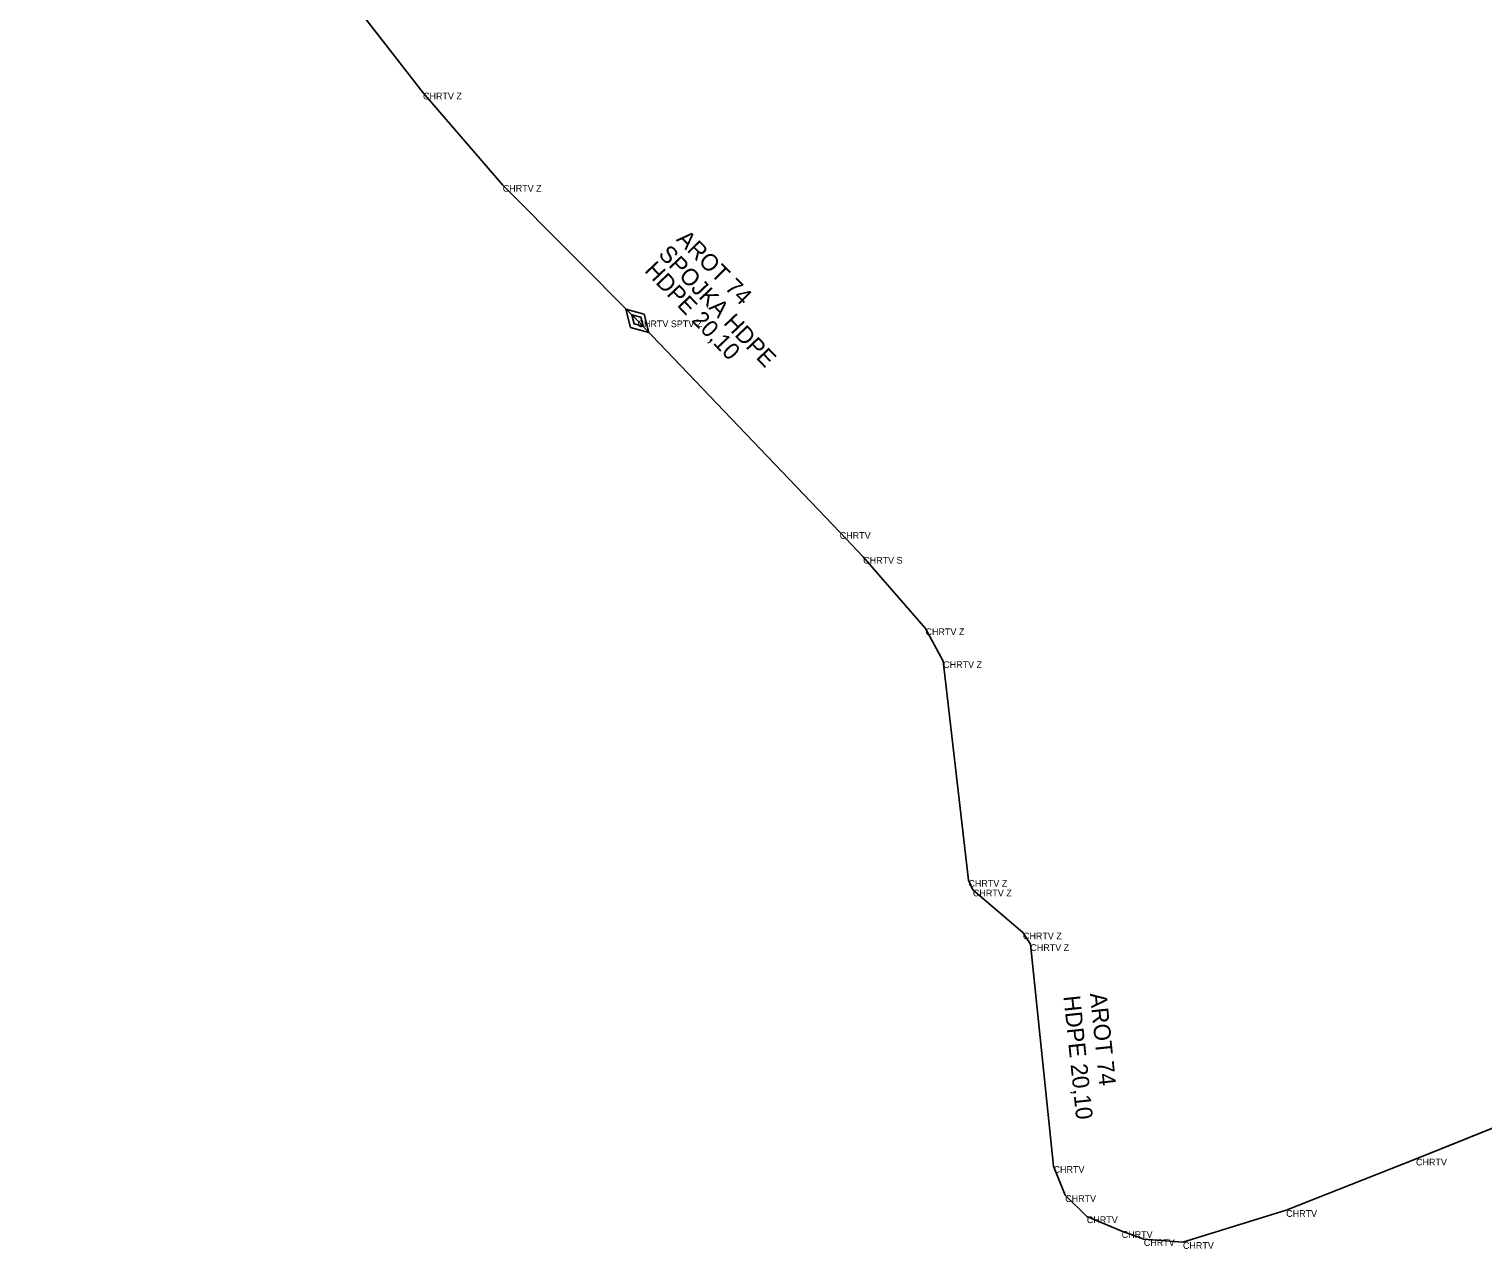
# Model space of a CAD drawing. Extents: x -651943 to -618711, y -1138561 to -1100552.
# Drawn here: x -641084.1 to -641019.1, y -1114735.4 to -1114680.8 of the extents above; entities that cross this region are included whole.
import ezdxf

# ---------------------------------------------------------------- set-up
doc = ezdxf.new("R2010")
doc.units = 0
for name, color, linetype in [('KT optika', 7, 'Continuous'), ('KT trasa', 7, 'Continuous'), ('KT zařízení', 7, 'Continuous')]:
    doc.layers.add(name, color=color, linetype=linetype)

# ---------------------------------------------------------------- blocks, each defined once
blk = doc.blocks.new('TVSPO_1')
at = {"layer": 'KT zařízení'}
for p, q in [((-0.074, 0.0016), (-0.0005, 0.0439)), ((-0.0005, -0.0409), (-0.074, 0.0016)), ((-0.0353, -0.0001), (0, 0.0203)), ((-0.0005, 0.0439), (0.0728, 0.0015)), ((0.0728, 0.0015), (-0.0005, -0.0409)), ((0, 0.0203), (0.0353, 0.0001)), ((0.0353, 0.0001), (0, -0.0204)), ((0, -0.0204), (-0.0353, -0.0001))]:
    blk.add_line(p, q, dxfattribs=at)

msp = doc.modelspace()

# ---------------------------------------------------------------- linework, layer by layer
at = {"layer": 'KT optika'}
for p, q in [((-641077, -1114670.16), (-641066.49, -1114683.68)), ((-641066.49, -1114683.68), (-641062.92, -1114687.81)), ((-641062.92, -1114687.81), (-641056.89, -1114693.87)), ((-641056.89, -1114693.87), (-641047.84, -1114703.34)), ((-641047.84, -1114703.34), (-641046.79, -1114704.45)), ((-641046.79, -1114704.45), (-641044, -1114707.65)), ((-641044, -1114707.65), (-641043.21, -1114709.12)), ((-641043.21, -1114709.12), (-641042.08, -1114718.91)), ((-641042.08, -1114718.91), (-641041.88, -1114719.34)), ((-641041.88, -1114719.34), (-641039.64, -1114721.26)), ((-641039.64, -1114721.26), (-641039.31, -1114721.78)), ((-641039.31, -1114721.78), (-641038.27, -1114731.71)), ((-641022.05, -1114731.38), (-641017.44, -1114729.53)), ((-641038.27, -1114731.71), (-641037.75, -1114733.01)), ((-641027.86, -1114733.68), (-641022.05, -1114731.38)), ((-641037.75, -1114733.01), (-641036.78, -1114733.96)), ((-641032.48, -1114735.11), (-641027.86, -1114733.68)), ((-641036.78, -1114733.96), (-641035.22, -1114734.62)), ((-641035.22, -1114734.62), (-641034.23, -1114734.98)), ((-641034.23, -1114734.98), (-641032.48, -1114735.11))]:
    msp.add_line(p, q, dxfattribs=at)
at = {"layer": 'KT trasa'}
for p, q in [((-641077, -1114670.16), (-641066.49, -1114683.68)), ((-641066.49, -1114683.68), (-641062.92, -1114687.81)), ((-641062.92, -1114687.81), (-641056.89, -1114693.87)), ((-641056.89, -1114693.87), (-641047.84, -1114703.34)), ((-641047.84, -1114703.34), (-641046.79, -1114704.45)), ((-641046.79, -1114704.45), (-641044, -1114707.65)), ((-641044, -1114707.65), (-641043.21, -1114709.12)), ((-641043.21, -1114709.12), (-641042.08, -1114718.91)), ((-641042.08, -1114718.91), (-641041.88, -1114719.34)), ((-641041.88, -1114719.34), (-641039.64, -1114721.26)), ((-641039.64, -1114721.26), (-641039.31, -1114721.78)), ((-641039.31, -1114721.78), (-641038.27, -1114731.71)), ((-641022.05, -1114731.38), (-641017.44, -1114729.53)), ((-641038.27, -1114731.71), (-641037.75, -1114733.01)), ((-641027.86, -1114733.68), (-641022.05, -1114731.38)), ((-641037.75, -1114733.01), (-641036.78, -1114733.96)), ((-641032.48, -1114735.11), (-641027.86, -1114733.68)), ((-641036.78, -1114733.96), (-641035.22, -1114734.62)), ((-641035.22, -1114734.62), (-641034.23, -1114734.98)), ((-641034.23, -1114734.98), (-641032.48, -1114735.11))]:
    msp.add_line(p, q, dxfattribs=at)
at = {"layer": 'KT zařízení'}
for points in [[(-641084.12, -1114661.06), (-641081.7, -1114663.89), (-641077, -1114670.16), (-641066.49, -1114683.68), (-641062.92, -1114687.81), (-641056.89, -1114693.87), (-641047.84, -1114703.34), (-641046.79, -1114704.45), (-641044, -1114707.65), (-641043.21, -1114709.12), (-641042.08, -1114718.91), (-641041.88, -1114719.34), (-641039.64, -1114721.26), (-641039.31, -1114721.78), (-641038.27, -1114731.71)], [(-641038.27, -1114731.71), (-641037.75, -1114733.01), (-641036.78, -1114733.96), (-641035.22, -1114734.62), (-641034.23, -1114734.98), (-641032.48, -1114735.11), (-641027.86, -1114733.68), (-641022.05, -1114731.38), (-641017.44, -1114729.53)]]:
    msp.add_lwpolyline(points, dxfattribs=at)

# ---------------------------------------------------------------- block references
at = {"layer": 'KT zařízení', "xscale": 10.000015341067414, "yscale": 10.000015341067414, "rotation": 135}
msp.add_blockref('TVSPO_1', (-641056.89, -1114693.87), dxfattribs=at)

# ---------------------------------------------------------------- texts
at = {"layer": 'KT zařízení'}
for s, p in [('CHRTV Z', (-641066.49, -1114683.98)), ('CHRTV Z', (-641062.92, -1114688.11)), ('CHRTV SPTV Z', (-641056.89, -1114694.17)), ('CHRTV', (-641047.84, -1114703.64)), ('CHRTV S', (-641046.79, -1114704.75)), ('CHRTV Z', (-641044, -1114707.95)), ('CHRTV Z', (-641043.21, -1114709.42)), ('CHRTV Z', (-641042.08, -1114719.21)), ('CHRTV Z', (-641041.88, -1114719.64)), ('CHRTV Z', (-641039.64, -1114721.56)), ('CHRTV Z', (-641039.31, -1114722.08)), ('CHRTV', (-641038.27, -1114732.01)), ('CHRTV', (-641022.05, -1114731.68)), ('CHRTV', (-641037.75, -1114733.31)), ('CHRTV', (-641027.86, -1114733.98)), ('CHRTV', (-641036.78, -1114734.26)), ('CHRTV', (-641035.22, -1114734.92)), ('CHRTV', (-641034.23, -1114735.28)), ('CHRTV', (-641032.48, -1114735.41))]:
    msp.add_text(s, height=0.3, dxfattribs=at).set_placement(p)
for s, rotation, p in [('AROT 74', 314.85783, (-641055.185, -1114690.269)), ('SPOJKA HDPE', 313.52086, (-641055.995, -1114690.936)), ('HDPE 20,10', 313.52086, (-641056.613, -1114691.663)), ('HDPE 20,10', 275.97897, (-641037.831, -1114724.111)), ('AROT 74', 275.97897, (-641036.65, -1114723.987))]:
    msp.add_text(s, height=0.75, rotation=rotation, dxfattribs=at).set_placement(p)

doc.saveas('drawing.dxf')
